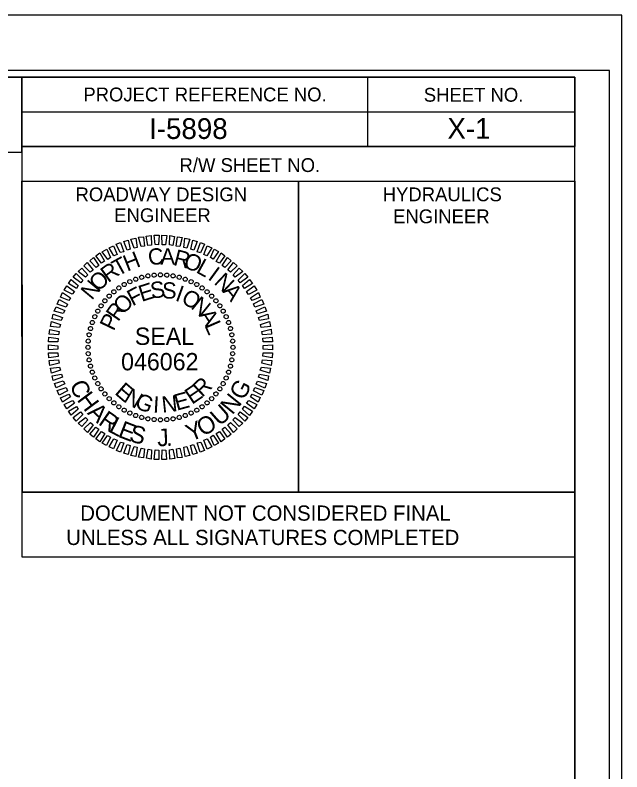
# Model space of a CAD drawing. Extents: x 2862872 to 2864765, y 971793 to 972888.
# Drawn here: x 2864336.1 to 2864555.6, y 972614.6 to 972888.3 of the extents above; entities that cross this region are included whole.
import ezdxf

# ---------------------------------------------------------------- set-up
doc = ezdxf.new("R2010")
doc.units = 0
for name, color, linetype in [('Default', 7, 'Continuous'), ('Old_Level_2', 7, 'Continuous'), ('Prop Dimension Text', 7, 'Continuous'), ('Sheet Cutting Line CELL', 7, 'Continuous'), ('Sheet Data Field CELL', 7, 'Continuous'), ('Sheet Plan CELL', 7, 'Continuous'), ('Sheet Plot Border Inside CELL', 7, 'Continuous'), ('Sheet Plot Border Outside CELL', 7, 'Continuous'), ('Sheet Sticker Exception Certification CELL', 7, 'Continuous')]:
    doc.layers.add(name, color=color, linetype=linetype)

msp = doc.modelspace()

# ---------------------------------------------------------------- linework, layer by layer
at = {"layer": 'Old_Level_2'}
for p, q in [((2864379.68, 972792.82), (2864379.68, 972792.82)), ((2864381.86, 972793.49), (2864381.86, 972793.49)), ((2864384.15, 972793.94), (2864384.15, 972793.94)), ((2864386.4, 972794.3), (2864386.4, 972794.3)), ((2864388.7, 972794.39), (2864388.7, 972794.39)), ((2864391, 972794.27), (2864391, 972794.27)), ((2864393.25, 972793.95), (2864393.25, 972793.95)), ((2864395.46, 972793.51), (2864395.46, 972793.51)), ((2864397.67, 972792.82), (2864397.67, 972792.82)), ((2864375.58, 972790.87), (2864375.58, 972790.87)), ((2864377.6, 972791.95), (2864377.6, 972791.95)), ((2864399.77, 972791.92), (2864399.77, 972791.92)), ((2864401.83, 972790.91), (2864401.83, 972790.91)), ((2864371.81, 972788.29), (2864371.81, 972788.29)), ((2864373.61, 972789.63), (2864373.61, 972789.63)), ((2864403.74, 972789.63), (2864403.74, 972789.63)), ((2864405.59, 972788.25), (2864405.59, 972788.25)), ((2864368.57, 972785.04), (2864368.57, 972785.04)), ((2864370.11, 972786.69), (2864370.11, 972786.69)), ((2864407.24, 972786.71), (2864407.24, 972786.71)), ((2864408.84, 972785.01), (2864408.84, 972785.01)), ((2864367.19, 972783.19), (2864367.19, 972783.19)), ((2864410.18, 972783.21), (2864410.18, 972783.21)), ((2864364.9, 972779.23), (2864364.9, 972779.23)), ((2864365.91, 972781.28), (2864365.91, 972781.28)), ((2864411.41, 972781.24), (2864411.41, 972781.24)), ((2864412.49, 972779.22), (2864412.49, 972779.22)), ((2864364, 972777.12), (2864364, 972777.12)), ((2864413.37, 972777.14), (2864413.37, 972777.14)), ((2864363.31, 972774.91), (2864363.31, 972774.91)), ((2864414.03, 972774.96), (2864414.03, 972774.96)), ((2864362.87, 972772.71), (2864362.87, 972772.71)), ((2864414.49, 972772.67), (2864414.49, 972772.67)), ((2864362.43, 972768.15), (2864362.43, 972768.15)), ((2864362.55, 972770.45), (2864362.55, 972770.45)), ((2864388.68, 972768.14), (2864388.68, 972768.14)), ((2864414.84, 972770.42), (2864414.84, 972770.42)), ((2864414.94, 972768.12), (2864414.94, 972768.12)), ((2864362.52, 972765.85), (2864362.52, 972765.85)), ((2864414.82, 972765.82), (2864414.82, 972765.82)), ((2864362.88, 972763.61), (2864362.88, 972763.61)), ((2864414.49, 972763.57), (2864414.49, 972763.57)), ((2864363.33, 972761.31), (2864363.33, 972761.31)), ((2864414.06, 972761.36), (2864414.06, 972761.36)), ((2864364, 972759.13), (2864364, 972759.13)), ((2864364.87, 972757.05), (2864364.87, 972757.05)), ((2864412.46, 972757.05), (2864412.46, 972757.05)), ((2864413.37, 972759.15), (2864413.37, 972759.15)), ((2864365.95, 972755.03), (2864365.95, 972755.03)), ((2864411.45, 972754.99), (2864411.45, 972754.99)), ((2864367.19, 972753.07), (2864367.19, 972753.07)), ((2864410.18, 972753.08), (2864410.18, 972753.08)), ((2864368.53, 972751.26), (2864368.53, 972751.26)), ((2864370.13, 972749.56), (2864370.13, 972749.56)), ((2864407.26, 972749.58), (2864407.26, 972749.58)), ((2864408.8, 972751.23), (2864408.8, 972751.23)), ((2864371.78, 972748.02), (2864371.78, 972748.02)), ((2864373.63, 972746.64), (2864373.63, 972746.64)), ((2864403.75, 972746.64), (2864403.75, 972746.64)), ((2864405.56, 972747.98), (2864405.56, 972747.98)), ((2864375.54, 972745.37), (2864375.54, 972745.37)), ((2864377.59, 972744.36), (2864377.59, 972744.36)), ((2864379.7, 972743.45), (2864379.7, 972743.45)), ((2864397.69, 972743.45), (2864397.69, 972743.45)), ((2864399.77, 972744.33), (2864399.77, 972744.33)), ((2864401.79, 972745.41), (2864401.79, 972745.41)), ((2864381.91, 972742.76), (2864381.91, 972742.76)), ((2864384.11, 972742.33), (2864384.11, 972742.33)), ((2864386.37, 972742), (2864386.37, 972742)), ((2864388.67, 972741.88), (2864388.67, 972741.88)), ((2864390.97, 972741.98), (2864390.97, 972741.98)), ((2864393.21, 972742.33), (2864393.21, 972742.33)), ((2864395.51, 972742.79), (2864395.51, 972742.79))]:
    msp.add_line(p, q, dxfattribs=at)
for points in [[(2864376.67, 972803.28), (2864375.41, 972806.39), (2864377.02, 972806.89), (2864377.76, 972803.66)], [(2864379.17, 972804), (2864378.01, 972807.28), (2864379.78, 972807.67), (2864380.26, 972804.28)], [(2864381.67, 972804.62), (2864380.77, 972807.95), (2864382.49, 972808.14), (2864382.92, 972804.8)], [(2864384.17, 972804.98), (2864383.54, 972808.31), (2864385.31, 972808.55), (2864385.42, 972805.16)], [(2864386.78, 972805.29), (2864386.46, 972808.68), (2864388.18, 972808.66), (2864388.03, 972805.26)], [(2864389.29, 972805.28), (2864389.23, 972808.68), (2864390.96, 972808.65), (2864390.55, 972805.25)], [(2864391.91, 972805.17), (2864392.06, 972808.57), (2864393.79, 972808.28), (2864393.16, 972804.98)], [(2864394.42, 972804.79), (2864394.84, 972808.15), (2864396.57, 972807.91), (2864395.68, 972804.66)], [(2864397.1, 972804.26), (2864397.56, 972807.67), (2864399.35, 972807.28), (2864398.2, 972804.02)], [(2864399.62, 972803.63), (2864400.35, 972806.88), (2864401.98, 972806.39), (2864400.73, 972803.28)], [(2864369.61, 972799.97), (2864367.63, 972802.75), (2864369.24, 972803.62), (2864370.6, 972800.61)], [(2864371.84, 972801.26), (2864370.12, 972804.16), (2864371.72, 972804.92), (2864372.98, 972801.75)], [(2864374.12, 972802.4), (2864372.71, 972805.41), (2864374.27, 972806.06), (2864375.42, 972802.73)], [(2864401.99, 972802.73), (2864403.13, 972806.04), (2864404.61, 972805.44), (2864403.2, 972802.38)], [(2864404.36, 972801.77), (2864405.61, 972804.88), (2864407.25, 972804.18), (2864405.52, 972801.22)], [(2864406.79, 972800.61), (2864408.15, 972803.62), (2864409.73, 972802.76), (2864407.79, 972800)], [(2864367.34, 972798.62), (2864365.36, 972801.25), (2864366.7, 972802.27), (2864368.48, 972799.27)], [(2864408.85, 972799.24), (2864410.63, 972802.3), (2864412, 972801.23), (2864410.01, 972798.63)], [(2864363.31, 972795.36), (2864360.97, 972797.62), (2864362.21, 972798.89), (2864364.3, 972796.11)], [(2864365.38, 972797.02), (2864363.09, 972799.49), (2864364.48, 972800.61), (2864366.36, 972797.71)], [(2864411.02, 972797.71), (2864412.9, 972800.62), (2864414.28, 972799.49), (2864412.03, 972796.99)], [(2864413.04, 972796.12), (2864415.13, 972798.88), (2864416.41, 972797.64), (2864414.04, 972795.35)], [(2864361.62, 972793.5), (2864358.92, 972795.6), (2864360.2, 972796.82), (2864362.44, 972794.35)], [(2864414.95, 972794.32), (2864417.15, 972796.82), (2864418.43, 972795.59), (2864415.75, 972793.5)], [(2864358.29, 972789.47), (2864355.44, 972791.19), (2864356.41, 972792.73), (2864358.95, 972790.47)], [(2864359.83, 972791.48), (2864357.07, 972793.47), (2864358.2, 972794.85), (2864360.54, 972792.43)], [(2864416.81, 972792.47), (2864419.18, 972794.87), (2864420.3, 972793.48), (2864417.56, 972791.44)], [(2864418.42, 972790.46), (2864420.94, 972792.7), (2864421.96, 972791.2), (2864419.06, 972789.48)], [(2864356.76, 972787.35), (2864353.81, 972788.86), (2864354.83, 972790.35), (2864357.58, 972788.3)], [(2864419.81, 972788.34), (2864422.55, 972790.38), (2864423.57, 972788.83), (2864420.56, 972787.31)], [(2864355.55, 972785.08), (2864352.54, 972786.33), (2864353.3, 972787.97), (2864356.16, 972786.08)], [(2864421.21, 972786.07), (2864424.11, 972787.95), (2864424.82, 972786.34), (2864421.86, 972785.08)], [(2864354.54, 972782.65), (2864351.28, 972783.8), (2864352.03, 972785.43), (2864355.04, 972783.81)], [(2864422.3, 972783.84), (2864425.35, 972785.46), (2864426.06, 972783.8), (2864422.84, 972782.7)], [(2864353.54, 972780.34), (2864350.28, 972781.22), (2864350.93, 972782.85), (2864354.09, 972781.44)], [(2864423.28, 972781.4), (2864426.45, 972782.81), (2864427.05, 972781.2), (2864423.82, 972780.31)], [(2864352.8, 972777.81), (2864349.54, 972778.44), (2864349.88, 972780.17), (2864353.19, 972778.92)], [(2864424.16, 972778.9), (2864427.49, 972780.16), (2864427.83, 972778.44), (2864424.55, 972777.81)], [(2864352.16, 972775.29), (2864348.91, 972775.65), (2864349.25, 972777.44), (2864352.56, 972776.4)], [(2864424.83, 972776.4), (2864428.11, 972777.45), (2864428.45, 972775.68), (2864425.17, 972775.31)], [(2864351.79, 972772.62), (2864348.44, 972772.87), (2864348.61, 972774.65), (2864352.03, 972773.88)], [(2864425.35, 972773.9), (2864428.73, 972774.69), (2864428.92, 972772.92), (2864425.58, 972772.65)], [(2864351.57, 972770.1), (2864348.17, 972770.15), (2864348.24, 972771.88), (2864351.65, 972771.36)], [(2864425.7, 972771.4), (2864429.09, 972771.87), (2864429.23, 972770.1), (2864425.83, 972770.14)], [(2864351.56, 972767.49), (2864348.17, 972767.27), (2864348.14, 972769.05), (2864351.54, 972768.74)], [(2864425.8, 972768.78), (2864429.2, 972769), (2864429.23, 972767.22), (2864425.82, 972767.53)], [(2864351.66, 972764.88), (2864348.27, 972764.4), (2864348.14, 972766.17), (2864351.54, 972766.13)], [(2864425.8, 972766.17), (2864429.2, 972766.12), (2864429.12, 972764.4), (2864425.71, 972764.91)], [(2864352.02, 972762.37), (2864348.63, 972761.58), (2864348.45, 972763.35), (2864351.79, 972763.62)], [(2864425.58, 972763.66), (2864428.93, 972763.4), (2864428.75, 972761.62), (2864425.34, 972762.4)], [(2864352.53, 972759.87), (2864349.26, 972758.82), (2864348.91, 972760.59), (2864352.2, 972760.96)], [(2864425.21, 972760.98), (2864428.45, 972760.62), (2864428.12, 972758.84), (2864424.81, 972759.88)], [(2864353.2, 972757.37), (2864349.88, 972756.11), (2864349.54, 972757.83), (2864352.82, 972758.46)], [(2864424.57, 972758.46), (2864427.82, 972757.84), (2864427.49, 972756.11), (2864424.17, 972757.35)], [(2864354.08, 972754.88), (2864350.92, 972753.46), (2864350.32, 972755.07), (2864353.54, 972755.97)], [(2864423.83, 972755.94), (2864427.09, 972755.05), (2864426.44, 972753.42), (2864423.27, 972754.83)], [(2864355.07, 972752.44), (2864352.01, 972750.81), (2864351.3, 972752.47), (2864354.53, 972753.58)], [(2864422.82, 972753.62), (2864426.09, 972752.47), (2864425.33, 972750.84), (2864422.32, 972752.46)], [(2864356.15, 972750.21), (2864353.26, 972748.32), (2864352.55, 972749.93), (2864355.51, 972751.19)], [(2864357.55, 972747.93), (2864354.82, 972745.89), (2864353.8, 972747.45), (2864356.8, 972748.96)], [(2864420.61, 972748.93), (2864423.56, 972747.41), (2864422.54, 972745.93), (2864419.79, 972747.97)], [(2864421.82, 972751.2), (2864424.82, 972749.94), (2864424.07, 972748.31), (2864421.21, 972750.19)], [(2864358.95, 972745.81), (2864356.43, 972743.57), (2864355.41, 972745.07), (2864358.31, 972746.79)], [(2864419.07, 972746.81), (2864421.93, 972745.08), (2864420.96, 972743.54), (2864418.41, 972745.8)], [(2864360.55, 972743.8), (2864358.19, 972741.4), (2864357.07, 972742.8), (2864359.8, 972744.83)], [(2864417.54, 972744.79), (2864420.29, 972742.8), (2864419.17, 972741.42), (2864416.82, 972743.84)], [(2864362.42, 972741.95), (2864360.21, 972739.45), (2864358.93, 972740.68), (2864361.62, 972742.77)], [(2864364.33, 972740.15), (2864362.23, 972737.39), (2864360.96, 972738.63), (2864363.32, 972740.92)], [(2864414.05, 972740.91), (2864416.39, 972738.65), (2864415.16, 972737.38), (2864413.07, 972740.16)], [(2864415.74, 972742.77), (2864418.45, 972740.68), (2864417.16, 972739.45), (2864414.92, 972741.92)], [(2864366.35, 972738.56), (2864364.46, 972735.66), (2864363.08, 972736.78), (2864365.34, 972739.28)], [(2864411.99, 972739.26), (2864414.28, 972736.79), (2864412.89, 972735.66), (2864411.01, 972738.56)], [(2864368.52, 972737.03), (2864366.74, 972733.97), (2864365.36, 972735.04), (2864367.36, 972737.64)], [(2864370.58, 972735.66), (2864369.22, 972732.65), (2864367.64, 972733.51), (2864369.58, 972736.27)], [(2864373.01, 972734.5), (2864371.75, 972731.39), (2864370.12, 972732.09), (2864371.85, 972735.05)], [(2864407.75, 972736.31), (2864409.73, 972733.52), (2864408.13, 972732.65), (2864406.77, 972735.66)], [(2864410.03, 972737.65), (2864412.01, 972735.02), (2864410.67, 972734), (2864408.89, 972737.01)], [(2864375.38, 972733.55), (2864374.23, 972730.23), (2864372.76, 972730.83), (2864374.17, 972733.89)], [(2864377.74, 972732.65), (2864377.02, 972729.39), (2864375.39, 972729.88), (2864376.64, 972732.99)], [(2864400.7, 972732.99), (2864401.95, 972729.88), (2864400.34, 972729.38), (2864399.61, 972732.61)], [(2864403.24, 972733.87), (2864404.66, 972730.87), (2864403.1, 972730.21), (2864401.94, 972733.54)], [(2864405.53, 972735.01), (2864407.25, 972732.11), (2864405.64, 972731.35), (2864404.38, 972734.52)], [(2864380.27, 972732.01), (2864379.8, 972728.6), (2864378.02, 972728.99), (2864379.16, 972732.25)], [(2864382.94, 972731.48), (2864382.53, 972728.13), (2864380.8, 972728.36), (2864381.69, 972731.62)], [(2864385.46, 972731.11), (2864385.31, 972727.7), (2864383.58, 972727.99), (2864384.2, 972731.29)], [(2864388.08, 972731), (2864388.14, 972727.6), (2864386.41, 972727.62), (2864386.82, 972731.03)], [(2864390.59, 972730.99), (2864390.91, 972727.59), (2864389.18, 972727.62), (2864389.33, 972731.02)], [(2864393.2, 972731.29), (2864393.83, 972727.96), (2864392.06, 972727.72), (2864391.94, 972731.11)], [(2864395.7, 972731.65), (2864396.59, 972728.32), (2864394.87, 972728.13), (2864394.45, 972731.47)], [(2864398.2, 972732.27), (2864399.35, 972729), (2864397.58, 972728.6), (2864397.11, 972731.99)]]:
    msp.add_lwpolyline(points, close=True, dxfattribs=at)
for centre, major_axis in [((2864377.6, 972791.91), (-0.318, 0.682)), ((2864379.71, 972792.78), (-0.258, 0.708)), ((2864381.89, 972793.47), (-0.195, 0.727)), ((2864384.13, 972793.97), (-0.131, 0.742)), ((2864386.4, 972794.26), (-0.066, 0.75)), ((2864388.68, 972794.36), (0, 0.753)), ((2864390.97, 972794.26), (0.066, 0.75)), ((2864393.24, 972793.97), (0.131, 0.742)), ((2864395.47, 972793.47), (0.195, 0.727)), ((2864397.65, 972792.78), (0.258, 0.708)), ((2864399.77, 972791.91), (0.318, 0.682)), ((2864373.64, 972789.62), (-0.432, 0.617)), ((2864375.57, 972790.85), (-0.376, 0.652)), ((2864401.8, 972790.85), (0.376, 0.652)), ((2864403.73, 972789.62), (0.432, 0.617)), ((2864370.14, 972786.68), (-0.532, 0.532)), ((2864371.82, 972788.23), (-0.484, 0.577)), ((2864405.54, 972788.23), (0.484, 0.577)), ((2864407.23, 972786.68), (0.532, 0.532)), ((2864368.59, 972784.99), (-0.577, 0.484)), ((2864408.77, 972784.99), (0.577, 0.484)), ((2864365.97, 972781.25), (-0.652, 0.376)), ((2864367.2, 972783.18), (-0.617, 0.432)), ((2864410.17, 972783.18), (0.617, 0.432)), ((2864411.4, 972781.25), (0.652, 0.376)), ((2864364.91, 972779.22), (-0.682, 0.318)), ((2864412.45, 972779.22), (0.682, 0.318)), ((2864364.04, 972777.11), (-0.708, 0.258)), ((2864413.33, 972777.11), (0.708, 0.258)), ((2864362.85, 972772.69), (-0.742, 0.131)), ((2864363.35, 972774.92), (-0.727, 0.195)), ((2864414.02, 972774.92), (0.727, 0.195)), ((2864414.51, 972772.69), (0.742, 0.131)), ((2864362.55, 972770.42), (-0.75, 0.066)), ((2864414.81, 972770.42), (0.75, 0.066)), ((2864362.46, 972768.14), (-0.753, 0)), ((2864414.91, 972768.14), (0.753, 0)), ((2864362.55, 972765.85), (-0.75, -0.066)), ((2864414.81, 972765.85), (0.75, -0.066)), ((2864362.85, 972763.58), (-0.742, -0.131)), ((2864414.51, 972763.58), (0.742, -0.131)), ((2864363.35, 972761.35), (-0.727, -0.195)), ((2864364.04, 972759.17), (-0.708, -0.258)), ((2864413.33, 972759.17), (0.708, -0.258)), ((2864414.02, 972761.35), (0.727, -0.195)), ((2864364.91, 972757.05), (-0.682, -0.318)), ((2864412.45, 972757.05), (0.682, -0.318)), ((2864365.97, 972755.02), (-0.652, -0.376)), ((2864411.4, 972755.02), (0.652, -0.376)), ((2864367.2, 972753.09), (-0.617, -0.432)), ((2864368.59, 972751.28), (-0.577, -0.484)), ((2864408.77, 972751.28), (0.577, -0.484)), ((2864410.17, 972753.09), (0.617, -0.432)), ((2864370.14, 972749.59), (-0.532, -0.532)), ((2864371.82, 972748.04), (-0.484, -0.577)), ((2864405.54, 972748.04), (0.484, -0.577)), ((2864407.23, 972749.59), (0.532, -0.532)), ((2864373.64, 972746.65), (-0.432, -0.617)), ((2864375.57, 972745.42), (-0.376, -0.652)), ((2864401.8, 972745.42), (0.376, -0.652)), ((2864403.73, 972746.65), (0.432, -0.617)), ((2864377.6, 972744.37), (-0.318, -0.682)), ((2864379.71, 972743.49), (-0.258, -0.708)), ((2864381.89, 972742.8), (-0.195, -0.727)), ((2864395.47, 972742.8), (0.195, -0.727)), ((2864397.65, 972743.49), (0.258, -0.708)), ((2864399.77, 972744.37), (0.318, -0.682)), ((2864384.13, 972742.31), (-0.131, -0.742)), ((2864386.4, 972742.01), (-0.066, -0.75)), ((2864388.68, 972741.91), (0, -0.753)), ((2864390.97, 972742.01), (0.066, -0.75)), ((2864393.24, 972742.31), (0.131, -0.742))]:
    msp.add_ellipse(centre, major_axis=major_axis, ratio=0.999708, dxfattribs=at)
at = {"layer": 'Prop Dimension Text'}
msp.add_lwpolyline([(2864188.67, 972838.79), (2864338.58, 972838.79), (2864338.58, 972865.84), (2864188.67, 972865.84)], close=True, dxfattribs=at)
at = {"layer": 'Sheet Cutting Line CELL'}
msp.add_line((2864555.63, 972888.32), (2862872.13, 972888.32), dxfattribs=at)
at = {"layer": 'Sheet Plan CELL'}
for p, q in [((2864463.6, 972865.77), (2864463.65, 972840.77)), ((2864463.6, 972865.77), (2864463.65, 972840.77)), ((2864338.57, 972853.29), (2864538.62, 972853.28)), ((2864338.57, 972853.29), (2864538.62, 972853.28)), ((2864338.58, 972840.75), (2864538.62, 972840.78)), ((2864338.58, 972840.75), (2864538.62, 972840.78)), ((2864338.58, 972840.75), (2864538.62, 972840.78)), ((2864338.58, 972840.75), (2864538.62, 972840.78)), ((2864338.58, 972840.75), (2864338.58, 972828.27)), ((2864338.58, 972840.75), (2864338.58, 972828.27)), ((2864338.58, 972840.75), (2864338.58, 972828.27)), ((2864338.58, 972840.75), (2864338.58, 972828.27)), ((2864438.63, 972828.27), (2864438.65, 972715.8)), ((2864438.63, 972828.27), (2864438.65, 972715.8))]:
    msp.add_line(p, q, dxfattribs=at)
for points in [[(2863038.62, 971815.83), (2863038.6, 972865.8), (2864338.58, 972865.84), (2864338.6, 972715.78), (2864538.63, 972715.77), (2864538.63, 971815.83)], [(2863038.62, 971815.83), (2863038.6, 972865.8), (2864338.58, 972865.84), (2864338.6, 972715.78), (2864538.63, 972715.77), (2864538.63, 971815.83)], [(2864538.66, 972865.83), (2863038.62, 972865.83), (2863038.62, 971815.83), (2864538.63, 971815.83)], [(2864538.66, 972865.83), (2863038.62, 972865.83), (2863038.62, 971815.83), (2864538.63, 971815.83)], [(2864338.58, 972865.84), (2864538.66, 972865.83), (2864538.62, 972840.78), (2864338.58, 972840.75)], [(2864338.58, 972865.84), (2864538.66, 972865.83), (2864538.62, 972840.78), (2864338.58, 972840.75)], [(2864338.58, 972828.27), (2864438.63, 972828.27), (2864438.63, 972715.75), (2864338.6, 972715.78)], [(2864338.58, 972828.27), (2864438.63, 972828.27), (2864438.63, 972715.75), (2864338.6, 972715.78)], [(2864438.63, 972828.27), (2864538.62, 972828.28), (2864538.63, 972715.77), (2864438.63, 972715.75)], [(2864438.63, 972828.27), (2864538.62, 972828.28), (2864538.63, 972715.77), (2864438.63, 972715.75)]]:
    msp.add_lwpolyline(points, close=True, dxfattribs=at)
at = {"layer": 'Sheet Plot Border Inside CELL'}
msp.add_lwpolyline([(2862885.13, 971813.32), (2864551.12, 971813.33), (2864551.13, 972868.32), (2862885.13, 972868.32)], close=True, dxfattribs=at)
at = {"layer": 'Sheet Plot Border Outside CELL'}
msp.add_lwpolyline([(2862872.13, 971793.32), (2864555.63, 971793.32), (2864555.63, 972888.32), (2862872.13, 972888.32)], close=True, dxfattribs=at)
msp.add_lwpolyline([(2862872.13, 971793.32), (2864555.63, 971793.32), (2864555.63, 972888.32), (2862872.13, 972888.32)], close=True, dxfattribs=at)
at = {"layer": 'Sheet Sticker Exception Certification CELL'}
for p, q in [((2864338.6, 972692.28), (2864338.6, 972715.78)), ((2864338.6, 972715.78), (2864538.63, 972715.78)), ((2864338.6, 972692.28), (2864338.6, 972715.78)), ((2864338.6, 972715.78), (2864538.63, 972715.78)), ((2864338.6, 972692.28), (2864338.6, 972715.78)), ((2864338.6, 972715.78), (2864538.63, 972715.78)), ((2864338.6, 972692.28), (2864338.6, 972715.78)), ((2864338.6, 972715.78), (2864538.63, 972715.78)), ((2864538.63, 972715.77), (2864538.63, 972692.27)), ((2864538.63, 972715.77), (2864538.63, 972692.27)), ((2864538.63, 972715.77), (2864538.63, 972692.27)), ((2864538.63, 972715.77), (2864538.63, 972692.27)), ((2864538.63, 972692.28), (2864338.6, 972692.28)), ((2864538.63, 972692.28), (2864338.6, 972692.28)), ((2864538.63, 972692.28), (2864338.6, 972692.28)), ((2864538.63, 972692.28), (2864338.6, 972692.28))]:
    msp.add_line(p, q, dxfattribs=at)

# ---------------------------------------------------------------- texts
at = {"layer": 'Default'}
for s, rotation, p in [('C', 297.1999, (2864355.56, 972754.41)), ('G', 61.7998, (2864418.79, 972748.64)), ('H', 306.6436, (2864358.26, 972749.16)), ('N', 51.2288, (2864414.71, 972743.45)), ('A', 316.4834, (2864361.95, 972744.23)), ('U', 41.4347, (2864410.13, 972739.38)), ('R', 325.1961, (2864365.88, 972740.46)), ('O', 30.0413, (2864404.03, 972735.71)), ('L', 332.5683, (2864369.62, 972737.76)), ('E', 338.7525, (2864373, 972735.88)), ('Y', 22.2426, (2864399.49, 972733.93)), ('S', 345.7591, (2864377.05, 972734.21)), ('J', 3.0321, (2864387.64, 972732.28)), ('.', 8.214, (2864390.88, 972732.33))]:
    msp.add_text(s, height=6.27, rotation=rotation, dxfattribs=at).set_placement(p)
at = {"layer": 'Old_Level_2'}
for s, rotation, p in [('C', 7.2199, (2864384.56, 972797.72)), ('A', 0.0203, (2864388.68, 972798.1)), ('R', 345.6211, (2864393.08, 972797.97)), ('T', 28.8198, (2864373.28, 972793.7)), ('H', 21.6195, (2864376.65, 972795.49)), ('O', 338.4212, (2864396.59, 972797.25)), ('R', 36.0205, (2864369.76, 972791.34)), ('L', 331.2209, (2864401.23, 972795.39)), ('O', 43.2217, (2864366.21, 972788.03)), ('I', 324.0201, (2864405.51, 972792.96)), ('N', 50.4235, (2864363.86, 972784.96)), ('N', 316.8189, (2864407.78, 972791.38)), ('F', 26.967, (2864378.54, 972782.92)), ('E', 17.6111, (2864381.86, 972784.54)), ('S', 8.2556, (2864385.45, 972785.7)), ('S', 358.9004, (2864389.21, 972785.82)), ('I', 340.1896, (2864393.72, 972785.17)), ('A', 309.6172, (2864410.92, 972788.34)), ('O', 45.6812, (2864375.14, 972779.77)), ('O', 330.8335, (2864395.82, 972784.47)), ('N', 321.4766, (2864399.36, 972782.44)), ('R', 55.0397, (2864373.36, 972777.18)), ('P', 64.3989, (2864371.74, 972773.8)), ('A', 302.7603, (2864402.39, 972779.78)), ('L', 293.4009, (2864404.49, 972776.2)), ('R', 43.4814, (2864403.75, 972749.83)), ('E', 319.2769, (2864371.82, 972751.47)), ('E', 34.1241, (2864400.08, 972747.31)), ('N', 328.634, (2864375.01, 972748.7)), ('E', 15.4118, (2864394.57, 972745.18)), ('G', 337.9902, (2864379.02, 972746.42)), ('I', 356.7012, (2864385.9, 972744.55)), ('N', 6.0564, (2864389.41, 972744.46))]:
    msp.add_text(s, height=5.9, rotation=rotation, dxfattribs=at).set_placement(p)
for s, height, p in [('SEAL', 6.273, (2864379.41, 972769.02)), ('046062', 6.275, (2864374.44, 972759.82))]:
    msp.add_text(s, height=height, dxfattribs=at).set_placement(p)
at = {"layer": 'Sheet Data Field CELL'}
for s, p in [('I-5898', (2864384.57, 972843.52)), ('X-1', (2864492.5, 972843.58))]:
    msp.add_text(s, height=7.5, rotation=0, dxfattribs=at).set_placement(p)
at = {"layer": 'Sheet Plan CELL'}
for s, height, p in [('PROJECT REFERENCE NO.', 5.0001, (2864360.78, 972857.12)), ('PROJECT REFERENCE NO.', 5.0001, (2864360.78, 972857.12)), ('SHEET NO.', 5, (2864483.95, 972857)), ('SHEET NO.', 5, (2864483.95, 972857)), ('R/W SHEET NO.', 5.0001, (2864395.58, 972831.57)), ('R/W SHEET NO.', 5.0001, (2864395.58, 972831.57)), ('ROADWAY DESIGN', 5.0001, (2864357.96, 972820.97)), ('ROADWAY DESIGN', 5.0001, (2864357.96, 972820.97)), ('HYDRAULICS', 5, (2864469.1, 972820.99)), ('HYDRAULICS', 5, (2864469.1, 972820.99)), ('ENGINEER', 5, (2864371.95, 972813.43)), ('ENGINEER', 5, (2864371.95, 972813.43)), ('ENGINEER', 5, (2864472.86, 972813.03)), ('ENGINEER', 5, (2864472.86, 972813.03))]:
    msp.add_text(s, height=height, rotation=0, dxfattribs=at).set_placement(p)
at = {"layer": 'Sheet Sticker Exception Certification CELL'}
for s, p in [('DOCUMENT NOT CONSIDERED FINAL', (2864359.67, 972705.43)), ('DOCUMENT NOT CONSIDERED FINAL', (2864359.67, 972705.43)), ('DOCUMENT NOT CONSIDERED FINAL', (2864359.67, 972705.43)), ('DOCUMENT NOT CONSIDERED FINAL', (2864359.67, 972705.43)), ('UNLESS ALL SIGNATURES COMPLETED', (2864354.59, 972696.63)), ('UNLESS ALL SIGNATURES COMPLETED', (2864354.59, 972696.63)), ('UNLESS ALL SIGNATURES COMPLETED', (2864354.59, 972696.63)), ('UNLESS ALL SIGNATURES COMPLETED', (2864354.59, 972696.63))]:
    msp.add_text(s, height=5.5, dxfattribs=at).set_placement(p)

doc.saveas('drawing.dxf')
